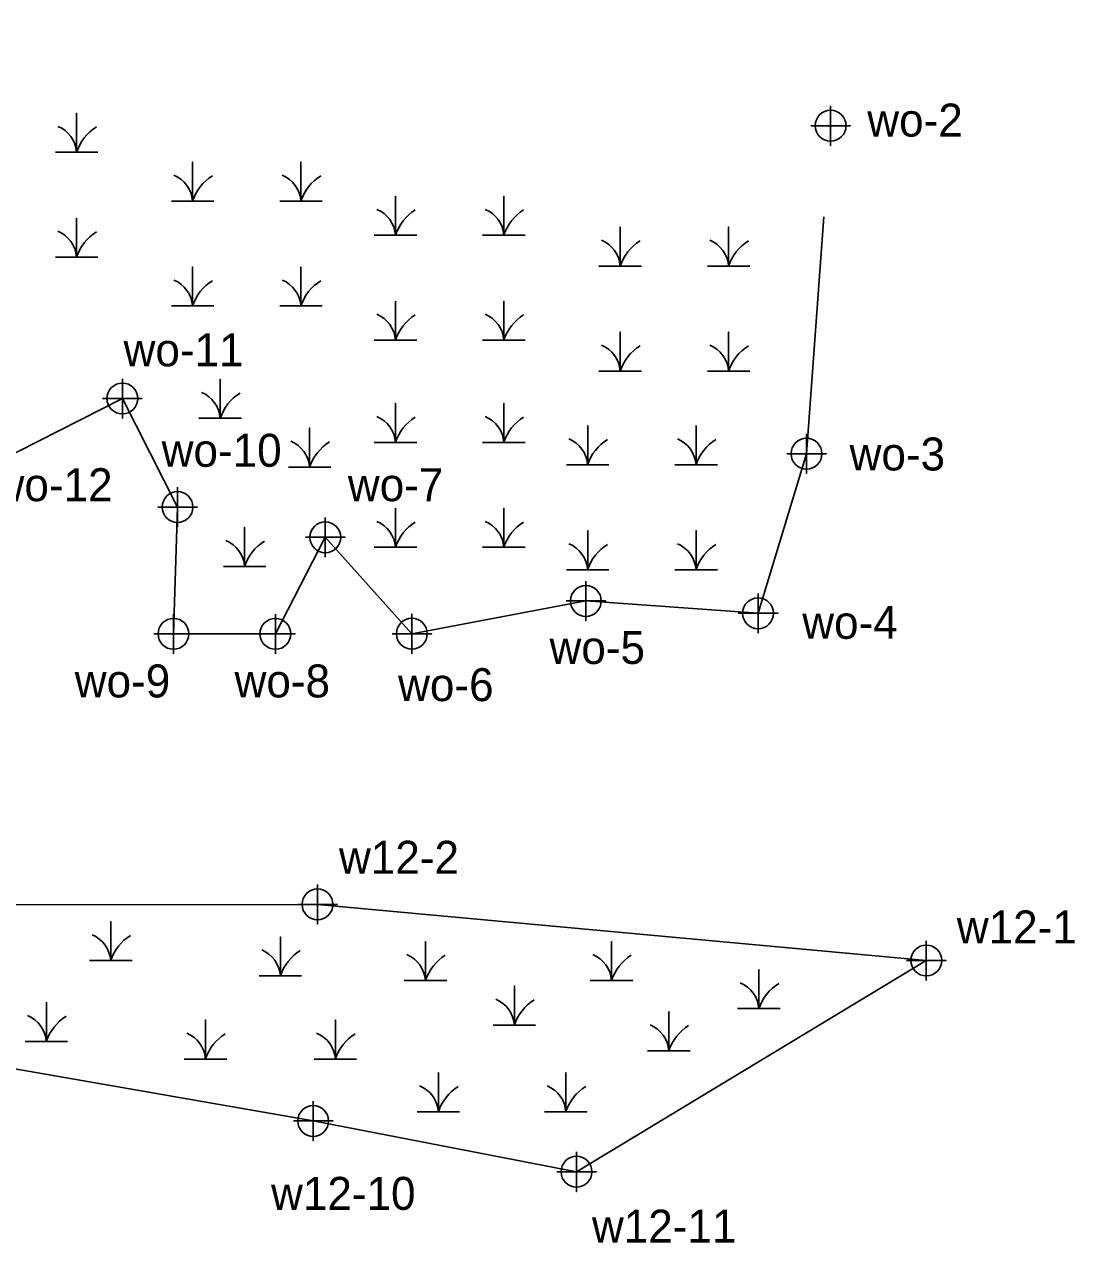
# Model space of a CAD drawing. Extents: x 2174810 to 2196950, y 76168 to 88270.
# Drawn here: x 2192275.9 to 2192435.3, y 86900 to 87084.8 of the extents above; entities that cross this region are included whole.
import ezdxf

# ---------------------------------------------------------------- set-up
doc = ezdxf.new("R2010")
doc.units = 0
for name, color, linetype in [('Exist Environmental Wetland Boundary', 7, 'Continuous'), ('Exist Environmental Wetland Boundary Cogo Point CELL', 7, 'Continuous'), ('Exist Hydro Jurisdictional Stream or Body of Water Mitigable Cogo Number', 7, 'Continuous'), ('Exist Hydro Swamp or Marsh', 7, 'Continuous')]:
    doc.layers.add(name, color=color, linetype=linetype)

msp = doc.modelspace()

# ---------------------------------------------------------------- linework, layer by layer
at = {"layer": 'Exist Environmental Wetland Boundary'}
msp.add_lwpolyline([(2192397.27, 87055.63), (2192394.63, 87019.68), (2192387.28, 86995.48), (2192361.14, 86997.34), (2192334.73, 86992.37), (2192321.6, 87007), (2192314.03, 86992.36), (2192298.56, 86992.36), (2192299.18, 87011.59), (2192290.81, 87028.06), (2192268.47, 87016.75), (2192269.64, 86994.86), (2192229.59, 86996.29), (2192215.81, 87002.68), (2192215.36, 87017.63), (2192195.8, 87023.15), (2192200.47, 87073.29), (2192220.73, 87075.01), (2192221.2, 87084.81), (2192254.26, 87078.79), (2192256.21, 87079.01)], dxfattribs=at)
msp.add_lwpolyline([(2192359.72, 86910.76), (2192412.81, 86942.8), (2192320.42, 86951.32), (2192243.31, 86951.23), (2192143.88, 86959.49), (2192045.01, 86974.5), (2191976.74, 86980.02), (2192028.37, 86965.72), (2192140.6, 86949.53), (2192233.5, 86933.52), (2192319.76, 86918.46)], close=True, dxfattribs=at)
at = {"layer": 'Exist Environmental Wetland Boundary Cogo Point CELL'}
for points in [[(2192398.28, 87072.43), (2192398.28, 87066.43), (2192398.28, 87069.43), (2192401.28, 87069.43), (2192395.28, 87069.43)], [(2192290.81, 87031.06), (2192290.81, 87025.06), (2192290.81, 87028.06), (2192293.81, 87028.06), (2192287.81, 87028.06)], [(2192394.63, 87022.68), (2192394.63, 87016.68), (2192394.63, 87019.68), (2192397.63, 87019.68), (2192391.63, 87019.68)], [(2192299.18, 87014.59), (2192299.18, 87008.59), (2192299.18, 87011.59), (2192302.18, 87011.59), (2192296.18, 87011.59)], [(2192321.6, 87010), (2192321.6, 87004), (2192321.6, 87007), (2192324.6, 87007), (2192318.6, 87007)], [(2192361.14, 87000.34), (2192361.14, 86994.34), (2192361.14, 86997.34), (2192364.14, 86997.34), (2192358.14, 86997.34)], [(2192387.28, 86998.48), (2192387.28, 86992.48), (2192387.28, 86995.48), (2192390.28, 86995.48), (2192384.28, 86995.48)], [(2192298.56, 86995.36), (2192298.56, 86989.36), (2192298.56, 86992.36), (2192301.56, 86992.36), (2192295.56, 86992.36)], [(2192314.03, 86995.36), (2192314.03, 86989.36), (2192314.03, 86992.36), (2192317.03, 86992.36), (2192311.03, 86992.36)], [(2192334.73, 86995.37), (2192334.73, 86989.37), (2192334.73, 86992.37), (2192337.73, 86992.37), (2192331.73, 86992.37)], [(2192320.42, 86954.32), (2192320.42, 86948.32), (2192320.42, 86951.32), (2192323.42, 86951.32), (2192317.42, 86951.32)], [(2192412.81, 86945.8), (2192412.81, 86939.8), (2192412.81, 86942.8), (2192415.81, 86942.8), (2192409.81, 86942.8)], [(2192319.76, 86921.46), (2192319.76, 86915.46), (2192319.76, 86918.46), (2192322.76, 86918.46), (2192316.76, 86918.46)], [(2192359.72, 86913.76), (2192359.72, 86907.76), (2192359.72, 86910.76), (2192362.72, 86910.76), (2192356.72, 86910.76)]]:
    msp.add_lwpolyline(points, dxfattribs=at)
for centre in [(2192398.28, 87069.43), (2192290.81, 87028.06), (2192394.63, 87019.68), (2192299.18, 87011.59), (2192321.6, 87007), (2192361.14, 86997.34), (2192387.28, 86995.48), (2192298.56, 86992.36), (2192314.03, 86992.36), (2192334.73, 86992.37), (2192320.42, 86951.32), (2192412.81, 86942.8), (2192319.76, 86918.46), (2192359.72, 86910.76)]:
    msp.add_circle(centre, 2.34, dxfattribs=at)
at = {"layer": 'Exist Hydro Swamp or Marsh'}
for points in [[(2192280.64, 87065.41), (2192283.86, 87065.41), (2192283.86, 87071.33), (2192283.86, 87065.41), (2192287.09, 87065.41)], [(2192298.24, 87058.01), (2192301.46, 87058.01), (2192301.46, 87063.93), (2192301.46, 87058.01), (2192304.69, 87058.01)], [(2192314.69, 87058.01), (2192317.91, 87058.01), (2192317.91, 87063.93), (2192317.91, 87058.01), (2192321.14, 87058.01)], [(2192329.02, 87052.82), (2192332.25, 87052.82), (2192332.25, 87058.74), (2192332.25, 87052.82), (2192335.47, 87052.82)], [(2192345.47, 87052.82), (2192348.7, 87052.82), (2192348.7, 87058.74), (2192348.7, 87052.82), (2192351.93, 87052.82)], [(2192280.64, 87049.5), (2192283.86, 87049.5), (2192283.86, 87055.41), (2192283.86, 87049.5), (2192287.09, 87049.5)], [(2192363.13, 87048.13), (2192366.36, 87048.13), (2192366.36, 87054.05), (2192366.36, 87048.13), (2192369.58, 87048.13)], [(2192379.58, 87048.13), (2192382.81, 87048.13), (2192382.81, 87054.05), (2192382.81, 87048.13), (2192386.03, 87048.13)], [(2192298.24, 87042.09), (2192301.46, 87042.09), (2192301.46, 87048.01), (2192301.46, 87042.09), (2192304.69, 87042.09)], [(2192314.69, 87042.09), (2192317.91, 87042.09), (2192317.91, 87048.01), (2192317.91, 87042.09), (2192321.14, 87042.09)], [(2192329.02, 87036.9), (2192332.25, 87036.9), (2192332.25, 87042.82), (2192332.25, 87036.9), (2192335.47, 87036.9)], [(2192345.47, 87036.9), (2192348.7, 87036.9), (2192348.7, 87042.82), (2192348.7, 87036.9), (2192351.93, 87036.9)], [(2192363.13, 87032.21), (2192366.36, 87032.21), (2192366.36, 87038.13), (2192366.36, 87032.21), (2192369.58, 87032.21)], [(2192379.58, 87032.21), (2192382.81, 87032.21), (2192382.81, 87038.13), (2192382.81, 87032.21), (2192386.03, 87032.21)], [(2192302.43, 87025.05), (2192305.66, 87025.05), (2192305.66, 87030.97), (2192305.66, 87025.05), (2192308.88, 87025.05)], [(2192329.02, 87021.4), (2192332.25, 87021.4), (2192332.25, 87027.32), (2192332.25, 87021.4), (2192335.47, 87021.4)], [(2192345.47, 87021.4), (2192348.7, 87021.4), (2192348.7, 87027.32), (2192348.7, 87021.4), (2192351.93, 87021.4)], [(2192316, 87017.65), (2192319.23, 87017.65), (2192319.23, 87023.56), (2192319.23, 87017.65), (2192322.45, 87017.65)], [(2192358.19, 87018.01), (2192361.42, 87018.01), (2192361.42, 87023.93), (2192361.42, 87018.01), (2192364.65, 87018.01)], [(2192374.65, 87018.01), (2192377.87, 87018.01), (2192377.87, 87023.93), (2192377.87, 87018.01), (2192381.1, 87018.01)], [(2192329.02, 87005.49), (2192332.25, 87005.49), (2192332.25, 87011.4), (2192332.25, 87005.49), (2192335.47, 87005.49)], [(2192345.47, 87005.49), (2192348.7, 87005.49), (2192348.7, 87011.4), (2192348.7, 87005.49), (2192351.93, 87005.49)], [(2192306.13, 87002.59), (2192309.36, 87002.59), (2192309.36, 87008.5), (2192309.36, 87002.59), (2192312.58, 87002.59)], [(2192358.19, 87002.09), (2192361.42, 87002.09), (2192361.42, 87008.01), (2192361.42, 87002.09), (2192364.65, 87002.09)], [(2192374.65, 87002.09), (2192377.87, 87002.09), (2192377.87, 87008.01), (2192377.87, 87002.09), (2192381.1, 87002.09)], [(2192285.81, 86942.78), (2192289.04, 86942.78), (2192289.04, 86948.7), (2192289.04, 86942.78), (2192292.27, 86942.78)], [(2192311.56, 86940.47), (2192314.79, 86940.47), (2192314.79, 86946.39), (2192314.79, 86940.47), (2192318.01, 86940.47)], [(2192333.58, 86939.76), (2192336.8, 86939.76), (2192336.8, 86945.68), (2192336.8, 86939.76), (2192340.03, 86939.76)], [(2192361.81, 86939.76), (2192365.04, 86939.76), (2192365.04, 86945.68), (2192365.04, 86939.76), (2192368.26, 86939.76)], [(2192384.18, 86935.5), (2192387.41, 86935.5), (2192387.41, 86941.41), (2192387.41, 86935.5), (2192390.63, 86935.5)], [(2192347.07, 86933.01), (2192350.3, 86933.01), (2192350.3, 86938.93), (2192350.3, 86933.01), (2192353.52, 86933.01)], [(2192276.05, 86930.52), (2192279.27, 86930.52), (2192279.27, 86936.44), (2192279.27, 86930.52), (2192282.5, 86930.52)], [(2192300.2, 86927.86), (2192303.42, 86927.86), (2192303.42, 86933.78), (2192303.42, 86927.86), (2192306.65, 86927.86)], [(2192319.91, 86927.86), (2192323.13, 86927.86), (2192323.13, 86933.78), (2192323.13, 86927.86), (2192326.36, 86927.86)], [(2192370.51, 86929.1), (2192373.74, 86929.1), (2192373.74, 86935.02), (2192373.74, 86929.1), (2192376.96, 86929.1)], [(2192335.53, 86919.86), (2192338.76, 86919.86), (2192338.76, 86925.78), (2192338.76, 86919.86), (2192341.98, 86919.86)], [(2192354.89, 86919.86), (2192358.11, 86919.86), (2192358.11, 86925.78), (2192358.11, 86919.86), (2192361.34, 86919.86)]]:
    msp.add_lwpolyline(points, dxfattribs=at)
for centre, radius, start, end in [((2192279.26, 87065.08), 4.61, 4.1403, 67.535), ((2192290.7, 87063.14), 7.21, 122.1274, 161.6222), ((2192296.86, 87057.67), 4.61, 4.1403, 67.535), ((2192308.3, 87055.73), 7.21, 122.1274, 161.6222), ((2192313.31, 87057.67), 4.61, 4.1403, 67.535), ((2192324.75, 87055.73), 7.21, 122.1274, 161.6222), ((2192327.65, 87052.49), 4.61, 4.1403, 67.535), ((2192339.09, 87050.55), 7.21, 122.1274, 161.6222), ((2192344.1, 87052.49), 4.61, 4.1403, 67.535), ((2192355.54, 87050.55), 7.21, 122.1274, 161.6222), ((2192279.26, 87049.16), 4.61, 4.1403, 67.535), ((2192290.7, 87047.22), 7.21, 122.1274, 161.6222), ((2192361.76, 87047.8), 4.61, 4.1403, 67.535), ((2192373.2, 87045.86), 7.21, 122.1274, 161.6222), ((2192378.21, 87047.8), 4.61, 4.1403, 67.535), ((2192389.65, 87045.86), 7.21, 122.1274, 161.6222), ((2192296.86, 87041.76), 4.61, 4.1403, 67.535), ((2192308.3, 87039.82), 7.21, 122.1274, 161.6222), ((2192313.31, 87041.76), 4.61, 4.1403, 67.535), ((2192324.75, 87039.82), 7.21, 122.1274, 161.6222), ((2192327.65, 87036.57), 4.61, 4.1403, 67.535), ((2192339.09, 87034.63), 7.21, 122.1274, 161.6222), ((2192344.1, 87036.57), 4.61, 4.1403, 67.535), ((2192355.54, 87034.63), 7.21, 122.1274, 161.6222), ((2192361.76, 87031.88), 4.61, 4.1403, 67.535), ((2192373.2, 87029.94), 7.21, 122.1274, 161.6222), ((2192378.21, 87031.88), 4.61, 4.1403, 67.535), ((2192389.65, 87029.94), 7.21, 122.1274, 161.6222), ((2192301.06, 87024.72), 4.61, 4.1403, 67.535), ((2192312.5, 87022.78), 7.21, 122.1274, 161.6222), ((2192327.65, 87021.07), 4.61, 4.1403, 67.535), ((2192339.09, 87019.13), 7.21, 122.1274, 161.6222), ((2192344.1, 87021.07), 4.61, 4.1403, 67.535), ((2192355.54, 87019.13), 7.21, 122.1274, 161.6222), ((2192314.63, 87017.31), 4.61, 4.1403, 67.535), ((2192326.07, 87015.37), 7.21, 122.1274, 161.6222), ((2192356.82, 87017.68), 4.61, 4.1403, 67.535), ((2192368.26, 87015.74), 7.21, 122.1274, 161.6222), ((2192373.27, 87017.68), 4.61, 4.1403, 67.535), ((2192384.71, 87015.74), 7.21, 122.1274, 161.6222), ((2192327.65, 87005.15), 4.61, 4.1403, 67.535), ((2192339.09, 87003.21), 7.21, 122.1274, 161.6222), ((2192344.1, 87005.15), 4.61, 4.1403, 67.535), ((2192355.54, 87003.21), 7.21, 122.1274, 161.6222), ((2192304.76, 87002.25), 4.61, 4.1403, 67.535), ((2192316.2, 87000.31), 7.21, 122.1274, 161.6222), ((2192356.82, 87001.76), 4.61, 4.1403, 67.535), ((2192368.26, 86999.82), 7.21, 122.1274, 161.6222), ((2192373.27, 87001.76), 4.61, 4.1403, 67.535), ((2192384.71, 86999.82), 7.21, 122.1274, 161.6222), ((2192284.44, 86942.45), 4.61, 4.1403, 67.535), ((2192295.88, 86940.51), 7.21, 122.1274, 161.6222), ((2192310.19, 86940.14), 4.61, 4.1403, 67.535), ((2192321.63, 86938.2), 7.21, 122.1274, 161.6222), ((2192332.2, 86939.43), 4.61, 4.1403, 67.535), ((2192343.64, 86937.49), 7.21, 122.1274, 161.6222), ((2192360.44, 86939.43), 4.61, 4.1403, 67.535), ((2192371.88, 86937.49), 7.21, 122.1274, 161.6222), ((2192382.81, 86935.16), 4.61, 4.1403, 67.535), ((2192394.25, 86933.22), 7.21, 122.1274, 161.6222), ((2192345.7, 86932.68), 4.61, 4.1403, 67.535), ((2192357.14, 86930.74), 7.21, 122.1274, 161.6222), ((2192274.67, 86930.19), 4.61, 4.1403, 67.535), ((2192286.11, 86928.25), 7.21, 122.1274, 161.6222), ((2192298.82, 86927.53), 4.61, 4.1403, 67.535), ((2192310.26, 86925.59), 7.21, 122.1274, 161.6222), ((2192318.53, 86927.53), 4.61, 4.1403, 67.535), ((2192329.97, 86925.59), 7.21, 122.1274, 161.6222), ((2192369.14, 86928.77), 4.61, 4.1403, 67.535), ((2192380.58, 86926.83), 7.21, 122.1274, 161.6222), ((2192334.16, 86919.53), 4.61, 4.1403, 67.535), ((2192345.6, 86917.59), 7.21, 122.1274, 161.6222), ((2192353.51, 86919.53), 4.61, 4.1403, 67.535), ((2192364.95, 86917.59), 7.21, 122.1274, 161.6222)]:
    msp.add_arc(centre, radius, start, end, dxfattribs=at)

# ---------------------------------------------------------------- texts
at = {"layer": 'Exist Hydro Jurisdictional Stream or Body of Water Mitigable Cogo Number'}
for s, p in [('wo-2', (2192403.85, 87067.79)), ('wo-11', (2192290.99, 87032.94)), ('wo-10', (2192296.77, 87017.7)), ('wo-3', (2192401.17, 87017.14)), ('wo-12', (2192271.11, 87012.48)), ('wo-7', (2192325.03, 87012.48)), ('wo-4', (2192393.98, 86991.6)), ('wo-5', (2192355.63, 86987.79)), ('wo-9', (2192283.58, 86982.71)), ('wo-8', (2192307.83, 86982.71)), ('wo-6', (2192332.65, 86982.15)), ('w12-2', (2192323.68, 86955.96)), ('w12-1', (2192417.44, 86945.39)), ('w12-10', (2192313.37, 86904.98)), ('w12-11', (2192362.07, 86900.01))]:
    msp.add_text(s, height=5, dxfattribs=at).set_placement(p)

doc.saveas('drawing.dxf')
